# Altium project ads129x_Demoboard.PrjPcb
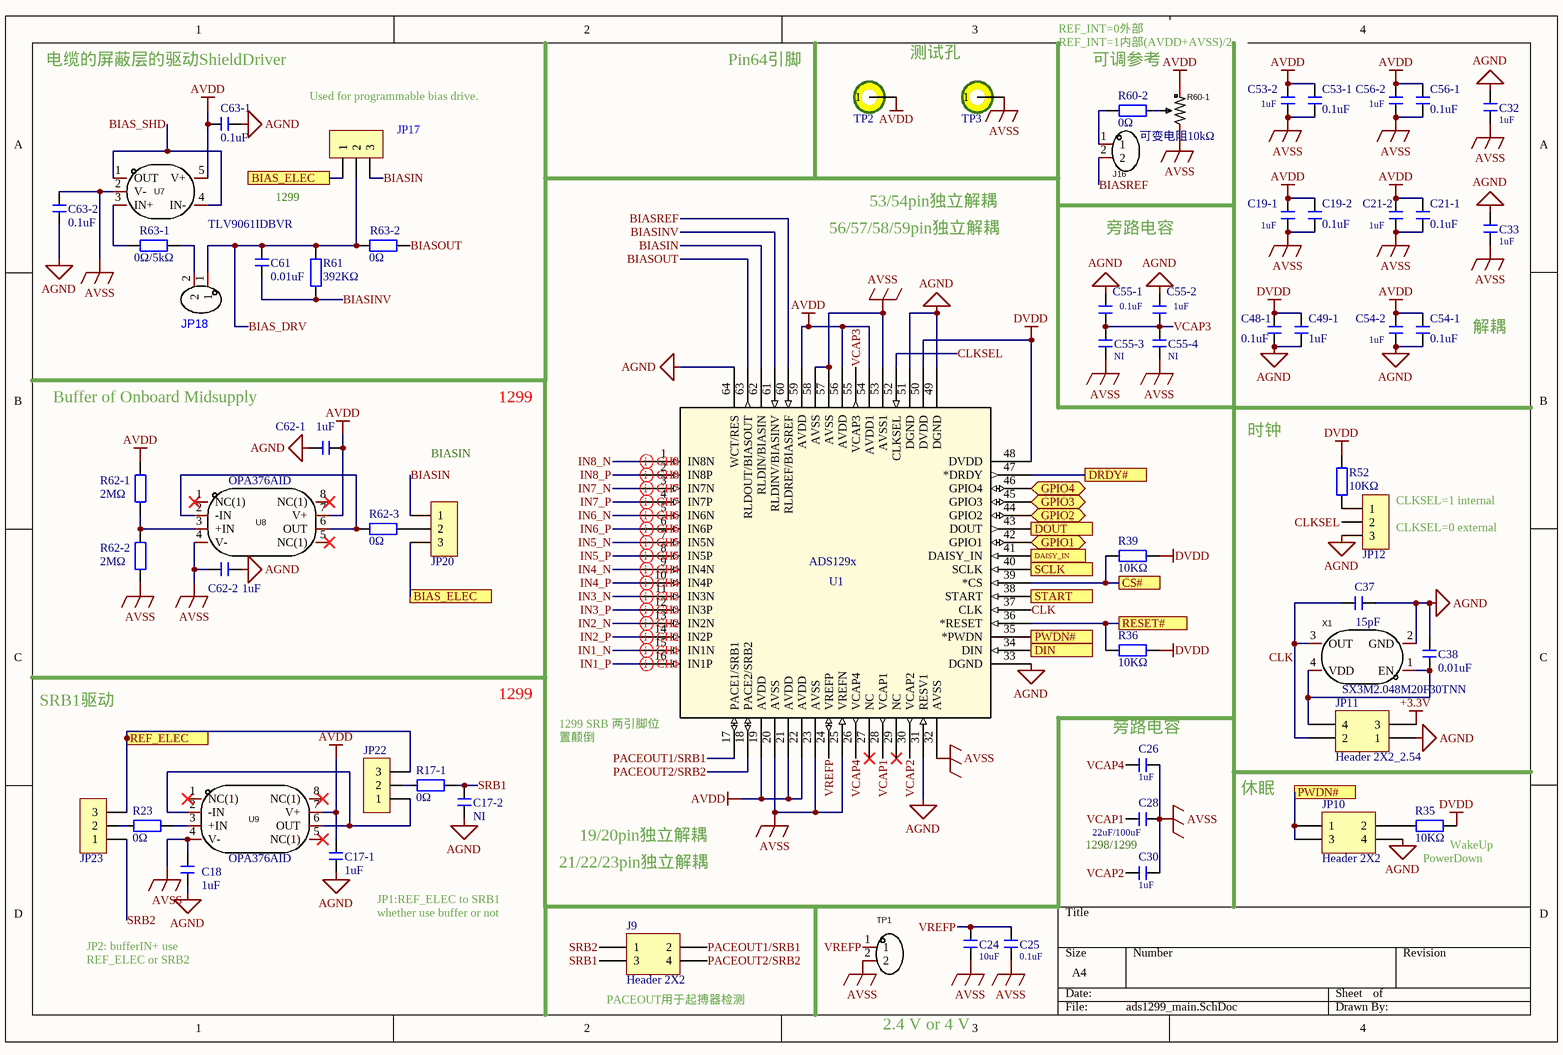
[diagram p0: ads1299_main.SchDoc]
4 sheets, 175 parts. Net scope: global (net labels, ports and power ports of the same name join across sheets).
Board file: ads1299.PcbDoc
Sheets:
  ads1299_main.SchDoc
  ads1299_Regulators.SchDoc
  ads1299_Ain.SchDoc
  ads1299_Interface.SchDoc

## Sheet ads1299_main.SchDoc
size A4

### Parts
C17-1  1uF  [0603C]
C17-2  NI  [0603C]
C18  1uF  [0603C]
C19-1  1uF  [0603C]
C19-2  0.1uF  [0603C]
C21-1  0.1uF  [0603C]
C21-2  1uF  [0603C]
C24  10uF  [0603C]
C25  0.1uF  [0603C]
C26  1uF  [0603C]
C28  22uF/100uF  [0603C]
C30  1uF  [0603C]
C32  1uF  [0603C]
C33  1uF  [0603C]
C37  15pF  [0603C]
C38  0.01uF  [0603C]
C48-1  0.1uF  [0603C]
C49-1  1uF  [0603C]
C53-1  0.1uF  [0603C]
C53-2  1uF  [0603C]
C54-1  0.1uF  [0603C]
C54-2  1uF  [0603C]
C55-1  0.1uF  [0603C]
C55-2  1uF  [0603C]
C55-3  NI  [0603C]
C55-4  NI  [0603C]
C56-1  0.1uF  [0603C]
C56-2  1uF  [0603C]
C61  0.01uF  [0603C]
C62-1  1uF  [0603C]
C62-2  1uF  [0603C]
C63-1  0.1uF  [0603C]
C63-2  0.1uF  [0603C]
J9  Header 2X2  [HDR2.54-LI-2x2P]
J16  Header_2P_2.54  [HDR2.54-LI-2P]  (value not drawn)
JP10  Header 2X2  [HDR2.54-LI-2x2P]
JP11  Header 2X2_2.54  [HDR2.54-LI-2x2P]
JP12  HDR-1X3  [HDR2.54-LI-3P]  (value not drawn)
JP17  HDR-1X3  [HDR2.54-LI-3P]  (value not drawn)
JP18  Header_2P_2.54  [HDR2.54-LI-2P]  (value not drawn)
JP20  HDR-1X3  [HDR2.54-LI-3P]  (value not drawn)
JP22  HDR-1X3  [HDR2.54-LI-3P]  (value not drawn)
JP23  HDR-1X3  [HDR2.54-LI-3P]  (value not drawn)
R17-1  0Ω  [0603R]
R23  0Ω  [0603R]
R35  10KΩ  [0603R]
R36  10KΩ  [0603R]
R39  10KΩ  [0603R]
R52  10KΩ  [0603R]
R60-1  可变电阻10kΩ  [RES-ADJ-TH_3362P]
R60-2  0Ω  [0603R]
R61  392KΩ  [0603R]
R62-1  2MΩ  [0603R]
R62-2  2MΩ  [0603R]
R62-3  0Ω  [0603R]
R63-1  0Ω/5kΩ  [0603R]
R63-2  0Ω  [0603R]
TP1  Header_2P_2.54  [HDR2.54-LI-2P]  (value not drawn)
TP2  测试点  [TestPoint_Pad]  (value not drawn)
TP3  测试点  [TestPoint_Pad]  (value not drawn)
U1  ADS129x  [LQFP-64]
U7  TLV9061IDBVR  [SOT23-5]
U8  OPA376AID  [SOIC-8]
U9  OPA376AID  [SOIC-8]
X1  SX3M2.048M20F30TNN  [OSC 3225-4P]

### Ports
BIAS_ELEC, CS#, DAISY_IN, DIN, DOUT, DRDY#, GPIO1 (bidir), GPIO2 (bidir), GPIO3 (bidir), GPIO4 (bidir), PWDN#, REF_ELEC, RESET#, SCLK, START

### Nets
+3.3V: JP11.3
AGND: C17-1.1 C17-2.1 C18.2 C32.1 C33.1 C37.1 C38.2 C48-1.1 C49-1.1 C54-1.1 C54-2.1 C55-1.1 C55-2.1 C62-1.1 C62-2.2 C63-1.1 C63-2.2 JP10.4 JP11.1 JP12.3 U1.31(RESV1) U1.33(DGND) U1.49(DGND) U1.51(DGND) U1.64(WCT/RES) X1.2(GND)
AVDD: C17-1.2 C19-1.2 C19-2.2 C21-1.2 C21-2.2 C53-1.2 C53-2.2 C54-1.2 C54-2.2 C56-1.2 C56-2.2 C62-1.2 C63-1.2 R60-1.1 R62-1.2 TP2.1 U1.19(AVDD) U1.21(AVDD) U1.22(AVDD) U1.54(AVDD1) U1.56(AVDD) U1.59(AVDD) U7.5(V+) U8.7(V+) U9.7(V+)
AVSS: C18.1 C19-1.1 C19-2.1 C21-1.1 C21-2.1 C24.2 C25.1 C26.1 C28.1 C30.1 C32.2 C33.2 C53-1.1 C53-2.1 C55-3.2 C55-4.2 C56-1.1 C56-2.1 C62-2.1 C63-2.1 R60-1.3 R62-2.1 TP1.2 TP3.1 U1.20(AVSS) U1.23(AVSS) U1.25(VREFN) U1.32(AVSS) U1.53(AVSS1) U1.57(AVSS) U1.58(AVSS) U7.2(V-) U8.4(V-) U9.4(V-)
DVDD: C48-1.2 C49-1.2 R35.1 R36.2 R39.1 R52.2 U1.48(DVDD) U1.50(DVDD)
BIAS_DRV: C61.1 JP17.2 JP18.1 R61.2 R63-2.2
BIAS_ELEC: JP17.1 JP20.3 ; port BIAS_ELEC
BIAS_SHD: U7.1(OUT) U7.4(IN-)
BIASIN: JP17.3 JP20.1 U1.62(RLDIN/BIASIN)
BIASINV: C61.2 R61.1 U1.61(RLDINV/BIASINV)
BIASOUT: R63-2.1 U1.63(RLDOUT/BIASOUT)
BIASREF: J16.2 U1.60(RLDREF/BIASREF)
CLK: C37.2 JP11.2 U1.37(CLK) X1.3(OUT)
CLKSEL: JP12.2 U1.52(CLKSEL)
CS#: R39.2 U1.39(*CS) ; port CS#
DAISY_IN: U1.41(DAISY_IN) ; port DAISY_IN
DIN: U1.34(DIN) ; port DIN
DOUT: U1.43(DOUT) ; port DOUT
DRDY#: U1.47(*DRDY) ; port DRDY#
GPIO1: U1.42(GPIO1) ; port GPIO1
GPIO2: U1.44(GPIO2) ; port GPIO2
GPIO3: U1.45(GPIO3) ; port GPIO3
GPIO4: U1.46(GPIO4) ; port GPIO4
IN1_N: U1.15(IN1N)
IN1_P: U1.16(IN1P)
IN2_N: U1.13(IN2N)
IN2_P: U1.14(IN2P)
IN3_N: U1.11(IN3N)
IN3_P: U1.12(IN3P)
IN4_N: U1.9(IN4N)
IN4_P: U1.10(IN4P)
IN5_N: U1.7(IN5N)
IN5_P: U1.8(IN5P)
IN6_N: U1.5(IN6N)
IN6_P: U1.6(IN6P)
IN7_N: U1.3(IN7N)
IN7_P: U1.4(IN7P)
IN8_N: U1.1(IN8N)
IN8_P: U1.2(IN8P)
PACEOUT1/SRB1: J9.2 U1.17(PACE1/SRB1)
PACEOUT2/SRB2: J9.4 U1.18(PACE2/SRB2)
PWDN#: JP10.1 JP10.3 U1.35(*PWDN) ; port PWDN#
REF_ELEC: JP22.3 JP23.3 ; port REF_ELEC
RESET#: R36.1 U1.36(*RESET) ; port RESET#
SCLK: U1.40(SCLK) ; port SCLK
SRB1: C17-2.2 J9.3 R17-1.2
SRB2: J9.1 JP23.1
START: U1.38(START) ; port START
VCAP1: C28.2 U1.28(VCAP1)
VCAP2: C30.2 U1.30(VCAP2)
VCAP3: C55-1.2 C55-2.2 C55-3.1 C55-4.1 U1.55(VCAP3)
VCAP4: C26.2 U1.26(VCAP4)
VREFP: C24.1 C25.2 TP1.1 U1.24(VREFP)
NetC38_1: C38.1 JP11.4 X1.1(EN) X1.4(VDD)
NetJ16_1: J16.1 R60-2.2
NetJP10_2: JP10.2 R35.2
NetJP12_1: JP12.1 R52.1
NetJP18_2: JP18.2 R63-1.2
NetJP20_2: JP20.2 R62-3.2
NetJP22_1: JP22.1 U9.2(-IN) U9.6(OUT)
NetJP22_2: JP22.2 R17-1.1
NetJP23_2: JP23.2 R23.1
NetR23_2: R23.2 U9.3(+IN)
NetR60-1_2: R60-1.2 R60-2.1
NetR62-1_1: R62-1.1 R62-2.2 U8.3(+IN)
NetR62-3_1: R62-3.1 U8.2(-IN) U8.6(OUT)
NetR63-1_1: R63-1.1 U7.3(IN+)

Not connected (* = marked no-connect by the designer): U1 27(NC)* 29(NC)*; U8 1(NC(1))* 5(NC(1))* 8(NC(1))*; U9 1(NC(1))* 5(NC(1))* 8(NC(1))*

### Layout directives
differential pair: IN1_N, IN1_P, IN2_N, IN2_P, IN3_N, IN3_P, IN4_N, IN4_P, IN5_N, IN5_P, IN6_N, IN6_P, IN7_N, IN7_P, IN8_N, IN8_P

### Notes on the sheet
- REF_INT=0外部
  REF_INT=1内部(AVDD+AVSS)/2
- 电缆的屏蔽层的驱动ShieldDriver
- Used for programmable bias drive.
- Pin64引脚
- 测试孔
- 可调参考
- 1299
- 56/57/58/59pin独立解耦
- 53/54pin独立解耦
- 旁路电容
- 解耦
- Buffer of Onboard Midsupply
- BIASIN
- 时钟
- (near JP12) CLKSEL=0 external
- CLKSEL=1 internal
- SRB1驱动
- (near U1) 1299 SRB 两引脚位置颠倒
- (near C26) 旁路电容
- 休眠
- 19/20pin独立解耦
- 1298/1299
- (near R35) PowerDown
- (near R35) WakeUp
- (near C17-1) JP1:REF_ELEC to SRB1
  whether use buffer or not
- 21/22/23pin独立解耦
- JP2: bufferIN+ use
  REF_ELEC or SRB2
- (near J9) PACEOUT用于起搏器检测
- 2.4 V or 4 V

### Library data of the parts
C17-1 C17-2 C18 C19-1 C19-2 C21-1 C21-2 C24-C26 C28 C30 C32 C33 C37 C38 C48-1 C49-1 C53-1 C53-2 C54-1 C54-2 C55-1-C55-4 C56-1 C56-2 C61 C62-1 C62-2 C63-1 C63-2 = C: Chip  Ceramic Capacitor; BOM名称: 无极性贴片电容; 版权归属: 源创客
J9 JP10 = Header 2X2: Header, 2-Pin, Dual row
J16 JP18 TP1 = Header_2P_2.54: Manufacturer: MOLEX; Name: 22284020; Add into BOM: yes; Pitch: 2.54mm; Pin Structure: 1x2P; Circluar Pins/Square Pins: 方针
JP11 = Header 2X2_2.54: Header, 2-Pin, Dual row
JP12 JP17 JP20 JP22 JP23 = Header 3: 3P接插件; 版权归属: 源创客
R17-1 R23 R35 R36 R39 R52 R60-2 R61 R62-1-R62-3 R63-1 R63-2 = R: 贴片电阻; 版权归属: 源创客
R60-1 = 3362P-1-103: Manufacturer: BOCHEN(博晨); Name: 10kΩ; Symbol: 3362P-1-103_C118956; Add into BOM: yes; Value: 10kΩ; Tolerance: ±10%
TP2 TP3 = TestPoint
U1 = ADS129x: ECG,EEG; Mfr_Name: Texas Instruments; Manufacturer_Part_Number: ADS131E08SPAG
U7 = TLV9061IDBVR: Manufacturer: TI(德州仪器); Add into BOM: yes
U8 U9 = OPA376AID: Manufacturer: TI(德州仪器); Add into BOM: yes
X1 = SX3M2.048M20F30TNN: Manufacturer: SCTF(星通时频); Name: 2.048MHz; Add into BOM: yes; Value: 2.048MHz; Frequency Stability: ±20ppm; Supply Voltage: 1.62V~3.63V; Supply Current (Max): 10mA; Output Type: CMOS

## Sheet ads1299_Regulators.SchDoc
size A4
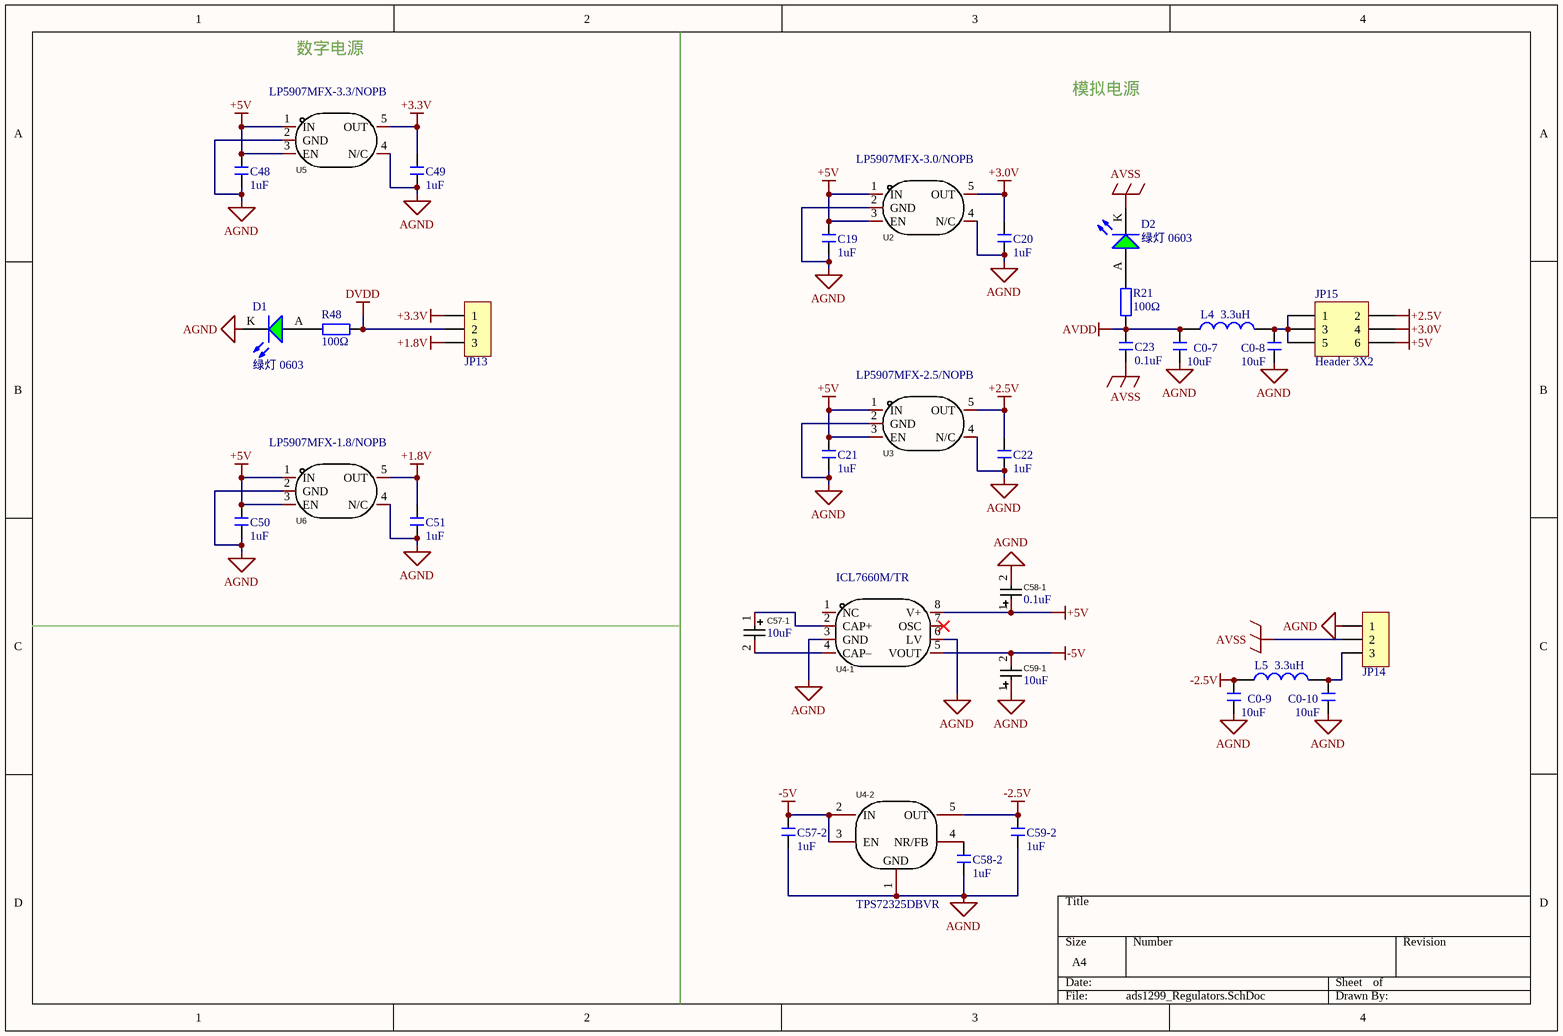
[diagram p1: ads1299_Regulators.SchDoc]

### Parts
C0-7  10uF  [0603C]
C0-8  10uF  [0603C]
C0-9  10uF  [0603C]
C0-10  10uF  [0603C]
C19  1uF  [0603C]
C20  1uF  [0603C]
C21  1uF  [0603C]
C22  1uF  [0603C]
C23  0.1uF  [0603C]
C48  1uF  [0603C]
C49  1uF  [0603C]
C50  1uF  [0603C]
C51  1uF  [0603C]
C57-1  10uF  [Tantalum_cap]
C57-2  1uF  [0603C]
C58-1  0.1uF  [Tantalum_cap]
C58-2  1uF  [0603C]
C59-1  10uF  [Tantalum_cap]
C59-2  1uF  [0603C]
D1  绿灯 0603  [LED 0603G]
D2  绿灯 0603  [LED 0603G]
JP13  HDR-1X3  [HDR2.54-LI-3P]  (value not drawn)
JP14  HDR-1X3  [HDR2.54-LI-3P]  (value not drawn)
JP15  Header 3X2  [HDR2.54-LI-2x3P]
L4  3.3uH  [L 1206]
L5  3.3uH  [L 1206]
R21  100Ω  [0603R]
R48  100Ω  [0603R]
U2  LP5907MFX-3.0/NOPB  [SOT23-5]
U3  LP5907MFX-2.5/NOPB  [SOT23-5]
U4-1  ICL7660M/TR  [SOIC-8]
U4-2  TPS72325DBVR  [SOT23-5]
U5  LP5907MFX-3.3/NOPB  [SOT23-5]
U6  LP5907MFX-1.8/NOPB  [SOT23-5]

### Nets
+1.8V: C51.2 JP13.3 U6.5(OUT)
+2.5V: C22.2 JP15.2 U3.5(OUT)
+3.0V: C20.2 JP15.4 U2.5(OUT)
+3.3V: C49.2 JP13.1 U5.5(OUT)
+5V: C19.2 C21.2 C48.2 C50.2 C58-1.1 JP15.6 U2.1(IN) U2.3(EN) U3.1(IN) U3.3(EN) U4-1.8(V+) U5.1(IN) U5.3(EN) U6.1(IN) U6.3(EN)
-2.5V: C0-9.2 C59-2.2 L5.1 U4-2.5(OUT)
-5V: C57-2.2 C59-1.2 U4-1.5(VOUT) U4-2.2(IN) U4-2.3(EN)
AGND: C0-7.1 C0-8.1 C0-9.1 C0-10.1 C19.1 C20.1 C21.1 C22.1 C48.1 C49.1 C50.1 C51.1 C57-2.1 C58-1.2 C58-2.1 C59-1.1 C59-2.1 D1.K JP14.1 U2.2(GND) U2.4(N/C) U3.2(GND) U3.4(N/C) U4-1.3(GND) U4-1.6(LV) U4-2.1(GND) U5.2(GND) U5.4(N/C) U6.2(GND) U6.4(N/C)
AVDD: C0-7.2 C23.2 L4.1 R21.2
AVSS: C23.1 D2.K JP14.2
DVDD: JP13.2 R48.2
NetC0-8_2: C0-8.2 JP15.1 JP15.3 JP15.5 L4.2
NetC0-10_2: C0-10.2 JP14.3 L5.2
NetC57-1_1: C57-1.1 U4-1.2(CAP+)
NetC57-1_2: C57-1.2 U4-1.4(CAP–)
NetC58-2_2: C58-2.2 U4-2.4(NR/FB)
NetD1_A: D1.A R48.1
NetD2_A: D2.A R21.1

Not connected (* = marked no-connect by the designer): U4-1 1(NC) 7(OSC)*

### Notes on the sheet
- 数字电源
- 模拟电源

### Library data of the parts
C0-7-C0-10 C19-C23 C48-C51 C57-2 C58-2 C59-2 = C: as C17-1 on sheet ads1299_main
C57-1 C58-1 C59-1 = Tantalum_cap: Manufacturer: Kyocera AVX; Name: 1uF; Symbol: TAJA105K035RNJ; Add into BOM: yes; Value: 1uF; Tolerance: ±10%; Rated Voltage: 35V; Equivalent Series Resistance(ESR): 7.5Ω@100kHz
D1 D2 = 0603 绿灯: 发光二极管
JP13 JP14 = Header 3: 3P接插件; 版权归属: 源创客
JP15 = Header 3X2: Header, 3-Pin, Dual row
L4 L5 = L 1206: 小功率贴片电感; 版权归属: 源创客
R21 R48 = R: 贴片电阻; 版权归属: 源创客
U2 U3 U5 U6 = LP5907MFX-3.3/NOPB: Manufacturer: TI(德州仪器); Add into BOM: yes; Output Type: 固定; Output Polarity: 正; Number of Outputs: 1; Maximum Input Voltage: 5.5V; Output Voltage: 3.3V; Dropout Voltage: 250mV@(250mA); Output Current: 250mA; Power Supply Rejection Ratio (PRSS): 90dB@(100Hz),60dB@(100kHz)
U4-1 = ICL7660M/TR: Manufacturer: HGSEMI(华冠); Add into BOM: yes
U4-2 = TPS72325DBVR: Manufacturer: TI(德州仪器); Add into BOM: yes; Output Type: 固定; Output Polarity: 负; Number of Outputs: 1; Maximum Input Voltage: 10V; Output Voltage: 2.5V; Dropout Voltage: 500mV@(200mA); Output Current: 200mA; Power Supply Rejection Ratio (PSRR): 65dB

## Sheet ads1299_Ain.SchDoc
size A4
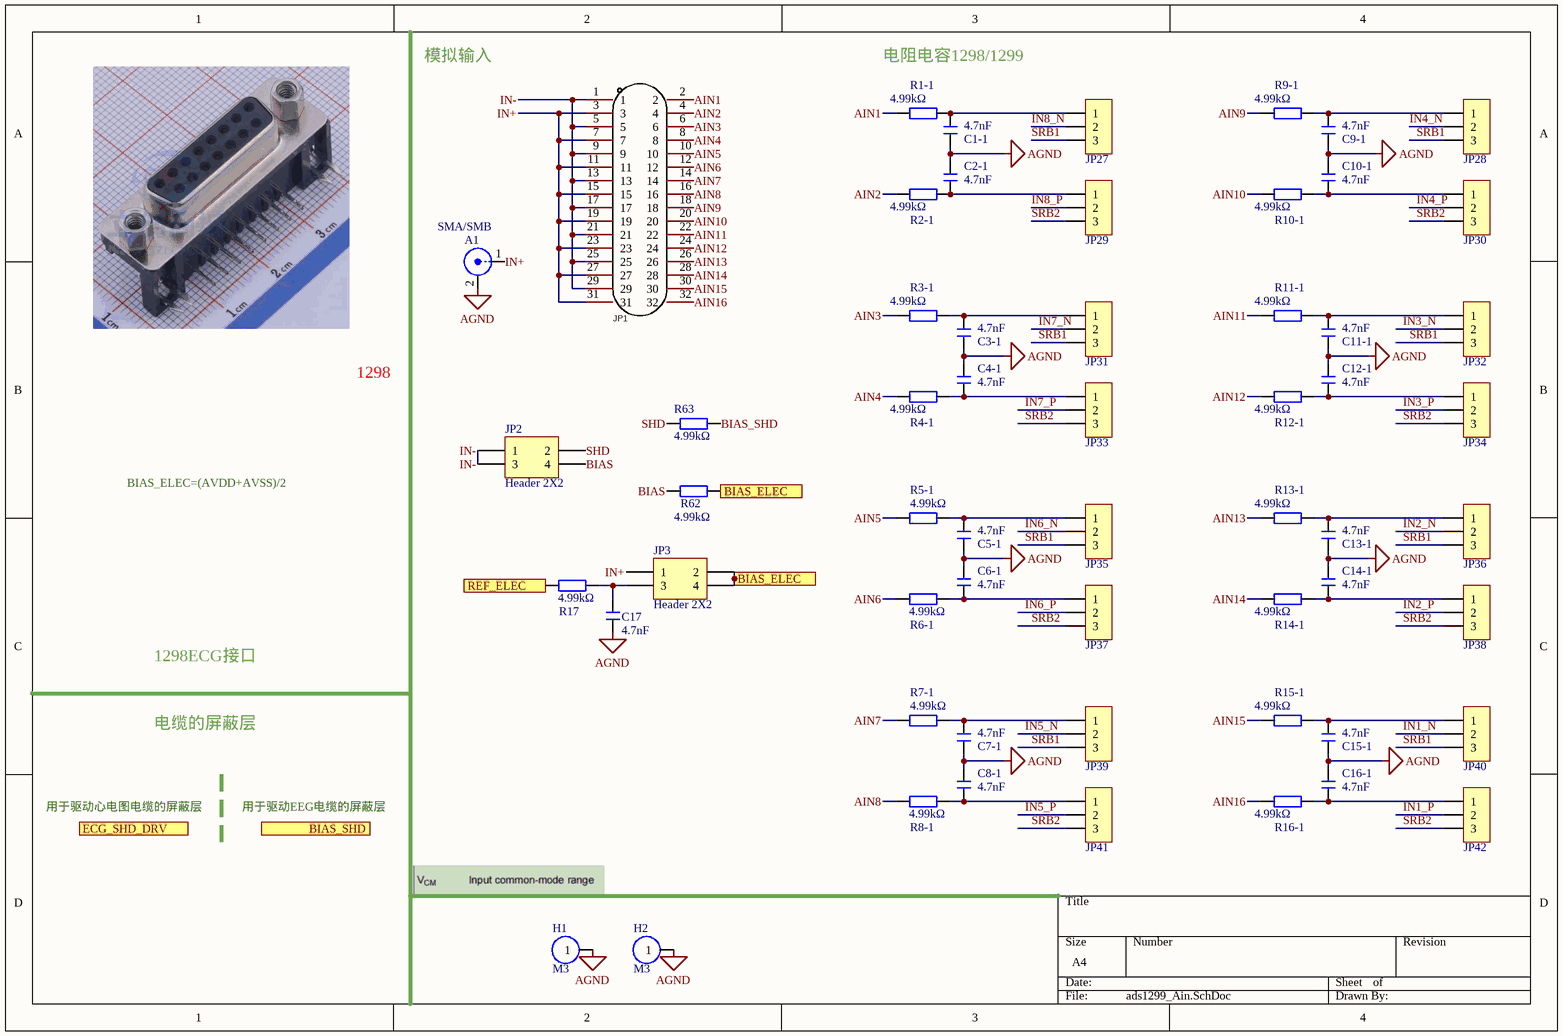
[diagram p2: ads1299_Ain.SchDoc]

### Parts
A1  SMA/SMB  [SMB_V-RJ45]
C1-1  4.7nF  [0603C]
C2-1  4.7nF  [0603C]
C3-1  4.7nF  [0603C]
C4-1  4.7nF  [0603C]
C5-1  4.7nF  [0603C]
C6-1  4.7nF  [0603C]
C7-1  4.7nF  [0603C]
C8-1  4.7nF  [0603C]
C9-1  4.7nF  [0603C]
C10-1  4.7nF  [0603C]
C11-1  4.7nF  [0603C]
C12-1  4.7nF  [0603C]
C13-1  4.7nF  [0603C]
C14-1  4.7nF  [0603C]
C15-1  4.7nF  [0603C]
C16-1  4.7nF  [0603C]
C17  4.7nF  [0603C]
H1  M3  [M3x4_L]
H2  M3  [M3x4_L]
JP1  B-2100S32P-B110  [HDR-TH_32P-P2.54-V-M-R2-C16-S2.54]  (value not drawn)
JP2  Header 2X2  [HDR2.54-LI-2x2P]
JP3  Header 2X2  [HDR2.54-LI-2x2P]
JP27  HDR-1X3  [HDR2.54-LI-3P]  (value not drawn)
JP28  HDR-1X3  [HDR2.54-LI-3P]  (value not drawn)
JP29  HDR-1X3  [HDR2.54-LI-3P]  (value not drawn)
JP30  HDR-1X3  [HDR2.54-LI-3P]  (value not drawn)
JP31  HDR-1X3  [HDR2.54-LI-3P]  (value not drawn)
JP32  HDR-1X3  [HDR2.54-LI-3P]  (value not drawn)
JP33  HDR-1X3  [HDR2.54-LI-3P]  (value not drawn)
JP34  HDR-1X3  [HDR2.54-LI-3P]  (value not drawn)
JP35  HDR-1X3  [HDR2.54-LI-3P]  (value not drawn)
JP36  HDR-1X3  [HDR2.54-LI-3P]  (value not drawn)
JP37  HDR-1X3  [HDR2.54-LI-3P]  (value not drawn)
JP38  HDR-1X3  [HDR2.54-LI-3P]  (value not drawn)
JP39  HDR-1X3  [HDR2.54-LI-3P]  (value not drawn)
JP40  HDR-1X3  [HDR2.54-LI-3P]  (value not drawn)
JP41  HDR-1X3  [HDR2.54-LI-3P]  (value not drawn)
JP42  HDR-1X3  [HDR2.54-LI-3P]  (value not drawn)
R1-1  4.99kΩ  [0603R]
R2-1  4.99kΩ  [0603R]
R3-1  4.99kΩ  [0603R]
R4-1  4.99kΩ  [0603R]
R5-1  4.99kΩ  [0603R]
R6-1  4.99kΩ  [0603R]
R7-1  4.99kΩ  [0603R]
R8-1  4.99kΩ  [0603R]
R9-1  4.99kΩ  [0603R]
R10-1  4.99kΩ  [0603R]
R11-1  4.99kΩ  [0603R]
R12-1  4.99kΩ  [0603R]
R13-1  4.99kΩ  [0603R]
R14-1  4.99kΩ  [0603R]
R15-1  4.99kΩ  [0603R]
R16-1  4.99kΩ  [0603R]
R17  4.99kΩ  [0603R]
R62  4.99kΩ  [0603R]
R63  4.99kΩ  [0603R]

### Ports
BIAS_ELEC, BIAS_SHD, ECG_SHD_DRV, REF_ELEC

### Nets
AGND: A1.2(Y) C1-1.1 C2-1.2 C3-1.1 C4-1.2 C5-1.1 C6-1.2 C7-1.1 C8-1.2 C9-1.1 C10-1.2 C11-1.1 C12-1.2 C13-1.1 C14-1.2 C15-1.1 C16-1.2 C17.1 H1.1 H2.1
AIN1: JP1.2 R1-1.1
AIN2: JP1.4 R2-1.1
AIN3: JP1.6 R3-1.1
AIN4: JP1.8 R4-1.1
AIN5: JP1.10 R5-1.1
AIN6: JP1.12 R6-1.1
AIN7: JP1.14 R7-1.1
AIN8: JP1.16 R8-1.1
AIN9: JP1.18 R9-1.1
AIN10: JP1.20 R10-1.1
AIN11: JP1.22 R11-1.1
AIN12: JP1.24 R12-1.1
AIN13: JP1.26 R13-1.1
AIN14: JP1.28 R14-1.1
AIN15: JP1.30 R15-1.1
AIN16: JP1.32 R16-1.1
BIAS: JP2.4 R62.1
BIAS_ELEC: JP3.2 JP3.4 R62.2 ; port BIAS_ELEC
BIAS_SHD: R63.2
IN1_N: JP40.2
IN1_P: JP42.2
IN2_N: JP36.2
IN2_P: JP38.2
IN3_N: JP32.2
IN3_P: JP34.2
IN4_N: JP28.2
IN4_P: JP30.2
IN5_N: JP39.2
IN5_P: JP41.2
IN6_N: JP35.2
IN6_P: JP37.2
IN7_N: JP31.2
IN7_P: JP33.2
IN8_N: JP27.2
IN8_P: JP29.2
IN+: A1.1(X) JP1.3 JP1.7 JP1.11 JP1.15 JP1.19 JP1.23 JP1.27 JP1.31 JP3.1
IN-: JP1.1 JP1.5 JP1.9 JP1.13 JP1.17 JP1.21 JP1.25 JP1.29 JP2.1 JP2.3
REF_ELEC: R17.1 ; port REF_ELEC
SHD: JP2.2 R63.1
SRB1: JP27.3 JP28.3 JP31.3 JP32.3 JP35.3 JP36.3 JP39.3 JP40.3
SRB2: JP29.3 JP30.3 JP33.3 JP34.3 JP37.3 JP38.3 JP41.3 JP42.3
NetC1-1_2: C1-1.2 JP27.1 R1-1.2
NetC2-1_1: C2-1.1 JP29.1 R2-1.2
NetC3-1_2: C3-1.2 JP31.1 R3-1.2
NetC4-1_1: C4-1.1 JP33.1 R4-1.2
NetC5-1_2: C5-1.2 JP35.1 R5-1.2
NetC6-1_1: C6-1.1 JP37.1 R6-1.2
NetC7-1_2: C7-1.2 JP39.1 R7-1.2
NetC8-1_1: C8-1.1 JP41.1 R8-1.2
NetC9-1_2: C9-1.2 JP28.1 R9-1.2
NetC10-1_1: C10-1.1 JP30.1 R10-1.2
NetC11-1_2: C11-1.2 JP32.1 R11-1.2
NetC12-1_1: C12-1.1 JP34.1 R12-1.2
NetC13-1_2: C13-1.2 JP36.1 R13-1.2
NetC14-1_1: C14-1.1 JP38.1 R14-1.2
NetC15-1_2: C15-1.2 JP40.1 R15-1.2
NetC16-1_1: C16-1.1 JP42.1 R16-1.2
NetC17_2: C17.2 JP3.3 R17.2

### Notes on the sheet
- 模拟输入
- 电阻电容1298/1299
- 1298
- BIAS_ELEC=(AVDD+AVSS)/2
- 1298ECG接口
- 电缆的屏蔽层
- 用于驱动心电图电缆的屏蔽层
- 用于驱动EEG电缆的屏蔽层

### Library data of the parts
A1 = SMB: SMB Straight Connector
C1-1 C2-1 C3-1 C4-1 C5-1 C6-1 C7-1 C8-1 C9-1 C10-1 C11-1 C12-1 C13-1 C14-1 C15-1 C16-1 C17 = C: as C17-1 on sheet ads1299_main
H1 H2 = M3: 铜柱孔; 版权归属: 封装库来自淘宝 ID：黄晶宝石
JP1 = Header2*16P: Manufacturer: Ckmtw(灿科盟); Symbol: 210S-2*16P L=11.6MMGold-plated black; Add into BOM: yes; Pitch: 2.54mm; Pin Structure: 2x16P
JP2 JP3 = Header 2X2: Header, 2-Pin, Dual row
JP27-JP42 = Header 3: 3P接插件; 版权归属: 源创客
R1-1 R2-1 R3-1 R4-1 R5-1 R6-1 R7-1 R8-1 R9-1 R10-1 R11-1 R12-1 R13-1 R14-1 R15-1 R16-1 R17 R62 R63 = R: 贴片电阻; 版权归属: 源创客

## Sheet ads1299_Interface.SchDoc
size A4
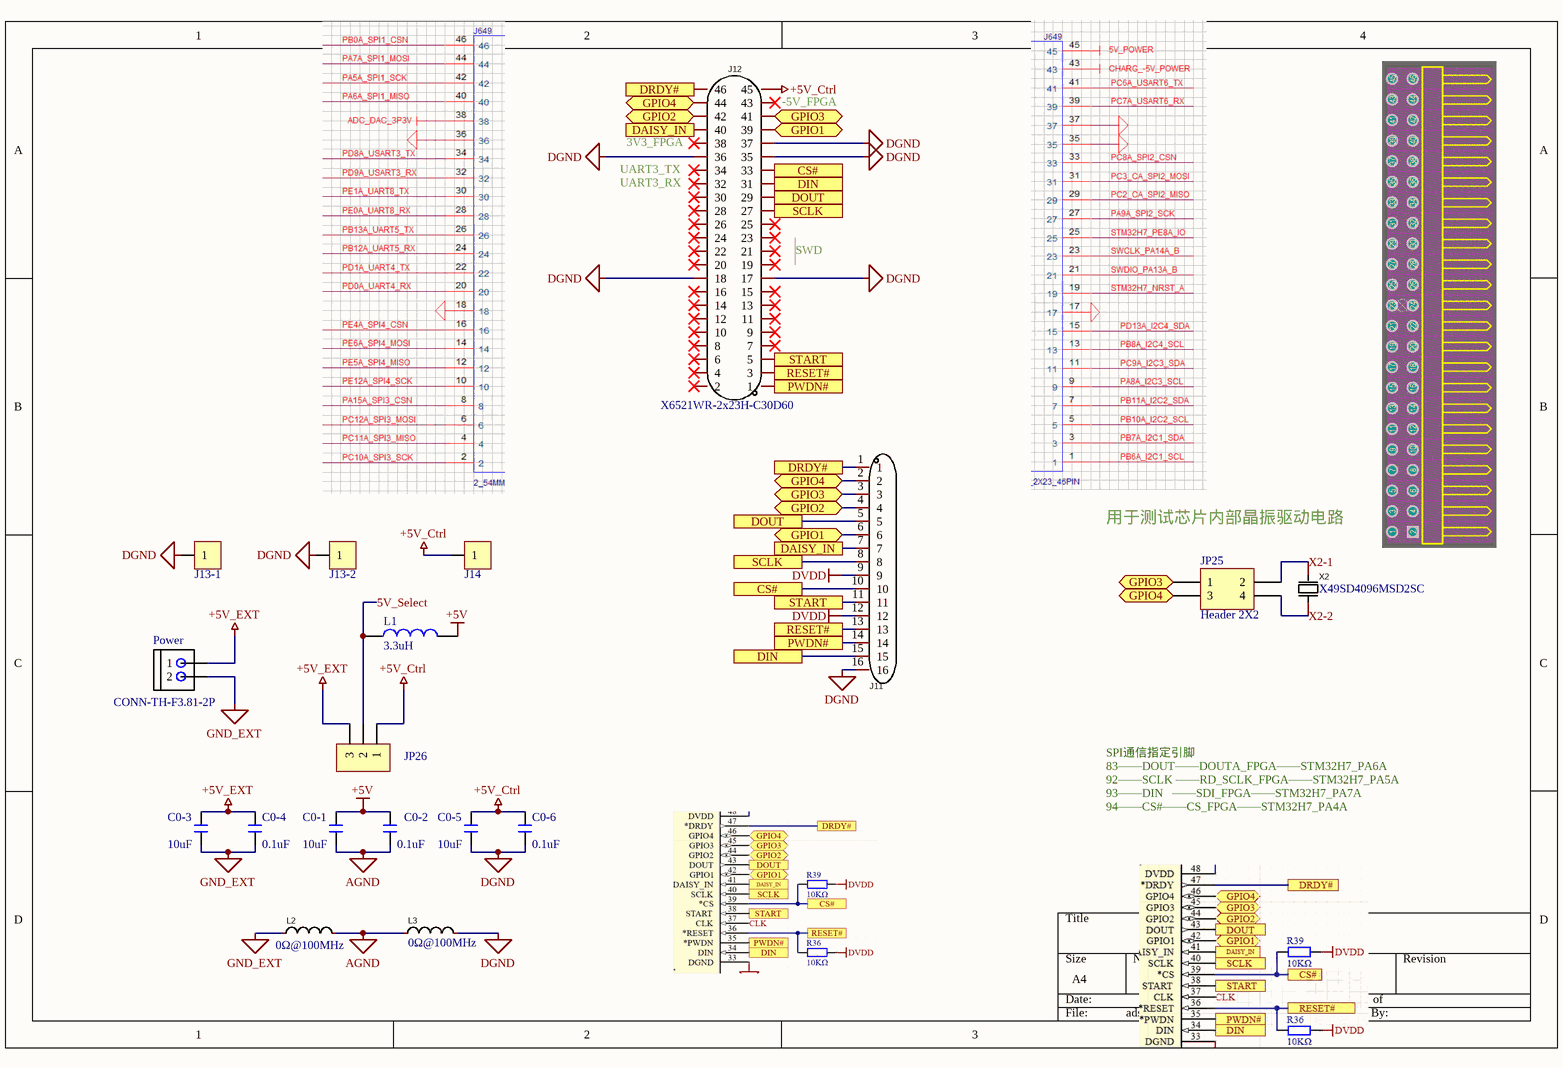
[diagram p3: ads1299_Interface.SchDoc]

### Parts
C0-1  10uF  [0603C]
C0-2  0.1uF  [0603C]
C0-3  10uF  [0603C]
C0-4  0.1uF  [0603C]
C0-5  10uF  [0603C]
C0-6  0.1uF  [0603C]
J11  KH-2.54PH180-1X16P-L11.5  [HDR-TH_16P-P2.54]  (value not drawn)
J12  X6521WR-2x23H-C30D60  [HDR-TH_2x23P-P2.54-Bent]
J13-1  Header_1P  [HDR-TH_1P]  (value not drawn)
J13-2  Header_1P  [HDR-TH_1P]  (value not drawn)
J14  Header_1P  [HDR-TH_1P]  (value not drawn)
JP25  Header 2X2  [HDR2.54-LI-2x2P]
JP26  HDR-1X3  [HDR2.54-LI-3P]  (value not drawn)
L1  3.3uH  [L 1206]
L2  0Ω@100MHz  [L 0603]
L3  0Ω@100MHz  [L 0603]
Power  CONN-TH-F3.81-2P  [CONN-TH_XY2500R-F-3.81-2P]
X2  X49SD4096MSD2SC  [HC-49US]

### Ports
CS#, DAISY_IN, DIN, DOUT, DRDY#, GPIO1 (bidir), GPIO2 (bidir), GPIO3 (bidir), GPIO4 (bidir), PWDN#, RESET#, SCLK, START

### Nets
+5V: C0-1.2 C0-2.2 L1.2
+5V_Ctrl: C0-5.2 C0-6.2 J12.45 J14.1 JP26.1
+5V_EXT: C0-3.2 C0-4.2 JP26.3 Power.1
AGND: C0-1.1 C0-2.1 L2.2 L3.1
DGND: C0-5.1 C0-6.1 J11.16 J12.17 J12.18 J12.35 J12.36 J12.37 J13-1.1 J13-2.1 L3.2
DVDD: J11.9 J11.12
GND_EXT: C0-3.1 C0-4.1 L2.1 Power.2
5V_Select: JP26.2 L1.1
CS#: J11.10 J12.33 ; port CS#
DAISY_IN: J11.7 J12.40 ; port DAISY_IN
DIN: J11.15 J12.31 ; port DIN
DOUT: J11.5 J12.29 ; port DOUT
DRDY#: J11.1 J12.46 ; port DRDY#
GPIO1: J11.6 J12.39 ; port GPIO1
GPIO2: J11.4 J12.42 ; port GPIO2
GPIO3: J11.3 J12.41 JP25.1 ; port GPIO3
GPIO4: J11.2 J12.44 JP25.3 ; port GPIO4
PWDN#: J11.14 J12.1 ; port PWDN#
RESET#: J11.13 J12.3 ; port RESET#
SCLK: J11.8 J12.27 ; port SCLK
START: J11.11 J12.5 ; port START
X2-1: JP25.2 X2.1(OSC1)
X2-2: JP25.4 X2.2(OSC2)

Not connected (* = marked no-connect by the designer): J12 2* 4* 6* 7* 8* 9* 10* 11* 12* 13* 14* 15* 16* 19* 20* 21* 22* 23* 24* 25* 26* 28* 30* 32* 34* 38* 43*

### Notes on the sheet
- (near J12) -5V_FPGA
- (near J12) UART3_RX
- (near J12) UART3_TX
- (near J12) 3V3_FPGA
- (near J12) SWD
- 用于测试芯片内部晶振驱动电路
- SPI通信指定引脚
  83——DOUT——DOUTA_FPGA——STM32H7_PA6A
  92——SCLK ——RD_SCLK_FPGA——STM32H7_PA5A
  93——DIN   ——SDI_FPGA——STM32H7_PA7A
  94——CS#——CS_FPGA——STM32H7_PA4A

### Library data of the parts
C0-1-C0-6 = C: as C17-1 on sheet ads1299_main
J11 = Header1x16: Manufacturer: kinghelm(金航标); Add into BOM: yes; Pitch: 2.54mm; Pin Structure: 1x16P; Circluar Pins/Square Pins: 方针; Current Rating (Max): 3A
J12 = Header_2.54mm_2x23P_Bent: Manufacturer: XKB Connectivity(中国星坤); Symbol: X6521WR-2×23H-C30D60; Add into BOM: yes; Pitch: 2.54mm; Pin Structure: 2x23P; Circluar Pins/Square Pins: 方针; Current Rating (Max): 3A; Voltage Rating (Max): 250V; Welding Temperature (Max): 260℃
JP25 = Header 2X2: Header, 2-Pin, Dual row
JP26 = Header 3_1: 3P接插件; 版权归属: 源创客
L1 = L 1206: 小功率贴片电感; 版权归属: 源创客
L2 L3 = CBW160808U000T: 磁珠; Manufacturer: FH(风华); Add into BOM: yes; Tolerance: 0~15Ω; DC Resistance: 80mΩ; Current Rating: 1A; Circuits: 1
X2 = Passive Oscillator: Manufacturer: YXC(扬兴晶振); Name: 4.096MHz; Symbol: X49SD4096MSD2SC-1; Add into BOM: yes; Crystal Type: 49S晶振; Value: 4.096MHz; Frequency Tolerance: ±20ppm; Frequency Stability: ±30ppm; Load Capacitance: 20pF

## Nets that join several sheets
+3.3V: ads1299_main (JP11.3), ads1299_Regulators (C49.2 JP13.1 U5.5)
+5V: ads1299_Regulators (15 pins), ads1299_Interface (C0-1.2 C0-2.2 L1.2)
AGND: ads1299_main (26 pins), ads1299_Regulators (30 pins), ads1299_Ain (20 pins), ads1299_Interface (C0-1.1 C0-2.1 L2.2 L3.1)
AVDD: ads1299_main (25 pins), ads1299_Regulators (C0-7.2 C23.2 L4.1 R21.2)
AVSS: ads1299_main (34 pins), ads1299_Regulators (C23.1 D2.K JP14.2)
DVDD: ads1299_main (8 pins), ads1299_Regulators (JP13.2 R48.2), ads1299_Interface (J11.9 J11.12)
BIAS_ELEC: ads1299_main (JP17.1 JP20.3), ads1299_Ain (JP3.2 JP3.4 R62.2)
BIAS_SHD: ads1299_main (U7.1 U7.4), ads1299_Ain (R63.2)
CS#: ads1299_main (R39.2 U1.39), ads1299_Interface (J11.10 J12.33)
DAISY_IN: ads1299_main (U1.41), ads1299_Interface (J11.7 J12.40)
DIN: ads1299_main (U1.34), ads1299_Interface (J11.15 J12.31)
DOUT: ads1299_main (U1.43), ads1299_Interface (J11.5 J12.29)
DRDY#: ads1299_main (U1.47), ads1299_Interface (J11.1 J12.46)
GPIO1: ads1299_main (U1.42), ads1299_Interface (J11.6 J12.39)
GPIO2: ads1299_main (U1.44), ads1299_Interface (J11.4 J12.42)
GPIO3: ads1299_main (U1.45), ads1299_Interface (J11.3 J12.41 JP25.1)
GPIO4: ads1299_main (U1.46), ads1299_Interface (J11.2 J12.44 JP25.3)
IN1_N: ads1299_main (U1.15), ads1299_Ain (JP40.2)
IN1_P: ads1299_main (U1.16), ads1299_Ain (JP42.2)
IN2_N: ads1299_main (U1.13), ads1299_Ain (JP36.2)
IN2_P: ads1299_main (U1.14), ads1299_Ain (JP38.2)
IN3_N: ads1299_main (U1.11), ads1299_Ain (JP32.2)
IN3_P: ads1299_main (U1.12), ads1299_Ain (JP34.2)
IN4_N: ads1299_main (U1.9), ads1299_Ain (JP28.2)
IN4_P: ads1299_main (U1.10), ads1299_Ain (JP30.2)
IN5_N: ads1299_main (U1.7), ads1299_Ain (JP39.2)
IN5_P: ads1299_main (U1.8), ads1299_Ain (JP41.2)
IN6_N: ads1299_main (U1.5), ads1299_Ain (JP35.2)
IN6_P: ads1299_main (U1.6), ads1299_Ain (JP37.2)
IN7_N: ads1299_main (U1.3), ads1299_Ain (JP31.2)
IN7_P: ads1299_main (U1.4), ads1299_Ain (JP33.2)
IN8_N: ads1299_main (U1.1), ads1299_Ain (JP27.2)
IN8_P: ads1299_main (U1.2), ads1299_Ain (JP29.2)
PWDN#: ads1299_main (JP10.1 JP10.3 U1.35), ads1299_Interface (J11.14 J12.1)
REF_ELEC: ads1299_main (JP22.3 JP23.3), ads1299_Ain (R17.1)
RESET#: ads1299_main (R36.1 U1.36), ads1299_Interface (J11.13 J12.3)
SCLK: ads1299_main (U1.40), ads1299_Interface (J11.8 J12.27)
SRB1: ads1299_main (C17-2.2 J9.3 R17-1.2), ads1299_Ain (8 pins)
SRB2: ads1299_main (J9.1 JP23.1), ads1299_Ain (8 pins)
START: ads1299_main (U1.38), ads1299_Interface (J11.11 J12.5)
